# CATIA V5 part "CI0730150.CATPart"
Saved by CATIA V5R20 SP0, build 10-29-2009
Part number: CI0730150
Bounding box of the stored display mesh (mm): x -29 to 29, y -25.758 to 195, z -29.41 to 34.617
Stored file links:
  C:\Users\Raffaele\Desktop\3D X SITO CF\BOLEX\19-INCLINED ASSEMBLY REF_CI\CI0730150.CATPart
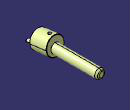
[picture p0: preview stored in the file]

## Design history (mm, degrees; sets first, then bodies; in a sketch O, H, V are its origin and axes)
Set1
  DatumSurface1 to DatumSurface16 "MANIFOLD_SOLID_BREP #395"
  DatumSurface17 to DatumSurface39 "MANIFOLD_SOLID_BREP #1144"
Body1 (main body)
